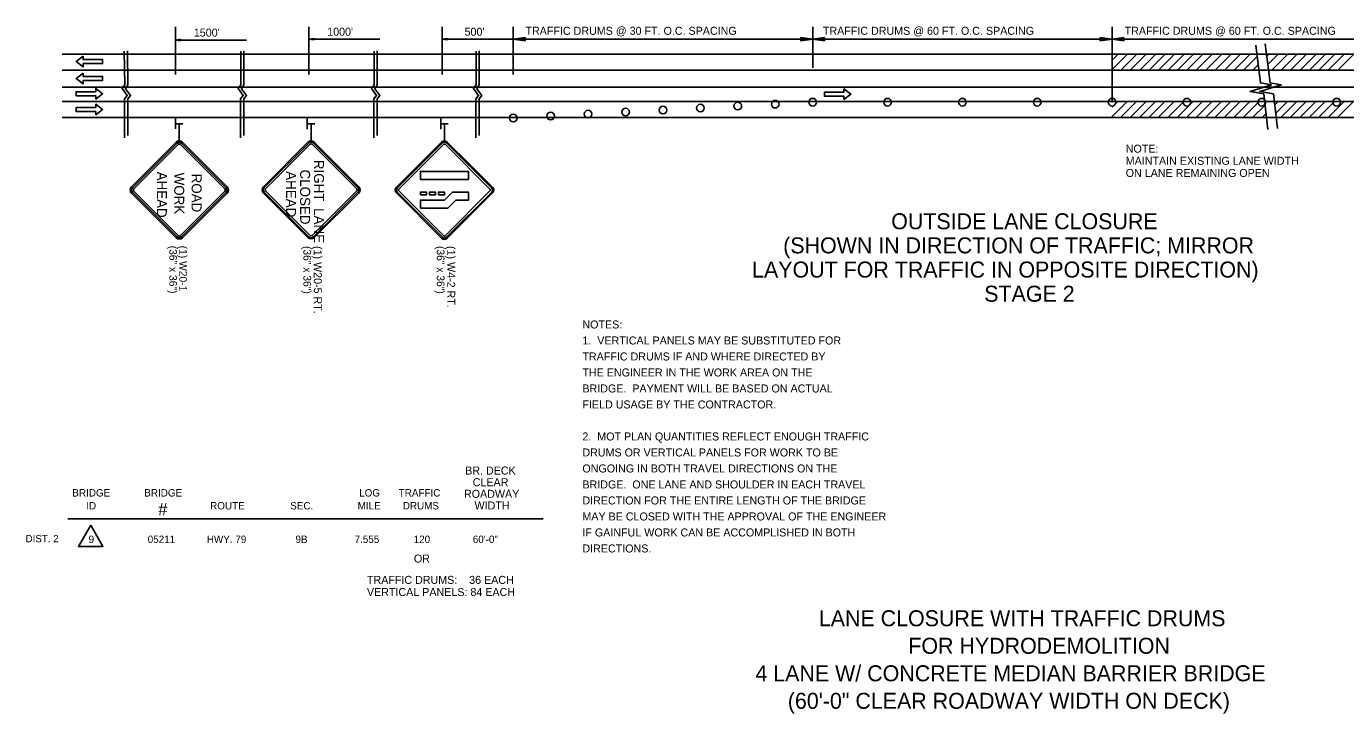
# Model space of a CAD drawing. Extents: x 1930579 to 1937984, y 596452 to 597630.
# Drawn here: x 1936426 to 1937415, y 596614 to 597129 of the extents above; entities that cross this region are included whole.
import ezdxf

# ---------------------------------------------------------------- set-up
doc = ezdxf.new("R2010")
doc.units = 0
for name, color, linetype in [('Default', 7, 'Continuous'), ('P_TC_Signs_Permanent', 7, 'Continuous'), ('P_TC_Signs_Temporary', 7, 'Continuous'), ('R_Border', 7, 'Continuous'), ('R_Striping', 7, 'Continuous')]:
    doc.layers.add(name, color=color, linetype=linetype)

msp = doc.modelspace()

# ---------------------------------------------------------------- linework, layer by layer
at = {"layer": 'Default'}
for p, q in [((1936537.79, 597129.19), (1936537.79, 597093.28)), ((1936637.79, 597129.19), (1936637.79, 597093.28)), ((1936737.79, 597129.19), (1936737.79, 597093.28)), ((1936791.02, 597129.19), (1936791.02, 597093.28)), ((1937015.53, 597129.19), (1937015.53, 597098.47)), ((1937240.04, 597129.19), (1937240.04, 597073.09)), ((1936541.62, 597119.78), (1936537.79, 597119.21)), ((1936537.79, 597119.21), (1936591.02, 597119.21)), ((1936541.62, 597118.63), (1936537.79, 597119.21)), ((1936541.62, 597119.68), (1936538.43, 597119.21)), ((1936541.62, 597118.73), (1936538.43, 597119.21)), ((1936541.62, 597119.59), (1936539.09, 597119.21)), ((1936541.62, 597118.83), (1936539.09, 597119.21)), ((1936541.62, 597119.49), (1936539.73, 597119.21)), ((1936541.62, 597118.92), (1936539.73, 597119.21)), ((1936541.62, 597119.39), (1936540.37, 597119.21)), ((1936541.62, 597119.02), (1936540.37, 597119.21)), ((1936541.62, 597119.3), (1936541.01, 597119.21)), ((1936541.62, 597119.12), (1936541.01, 597119.21)), ((1936541.62, 597118.63), (1936541.62, 597119.78)), ((1936641.62, 597120.46), (1936637.79, 597119.89)), ((1936637.79, 597119.89), (1936691.02, 597119.89)), ((1936641.62, 597119.31), (1936637.79, 597119.89)), ((1936641.62, 597120.36), (1936638.43, 597119.89)), ((1936641.62, 597119.41), (1936638.43, 597119.89)), ((1936641.62, 597120.27), (1936639.09, 597119.89)), ((1936641.62, 597119.51), (1936639.09, 597119.89)), ((1936641.62, 597120.17), (1936639.73, 597119.89)), ((1936641.62, 597119.6), (1936639.73, 597119.89)), ((1936641.62, 597120.07), (1936640.37, 597119.89)), ((1936641.62, 597119.7), (1936640.37, 597119.89)), ((1936641.62, 597119.98), (1936641.01, 597119.89)), ((1936641.62, 597119.8), (1936641.01, 597119.89)), ((1936641.62, 597119.31), (1936641.62, 597120.46)), ((1936741.62, 597120.46), (1936737.79, 597119.89)), ((1936737.79, 597119.89), (1936791.02, 597119.89)), ((1936741.62, 597119.31), (1936737.79, 597119.89)), ((1936741.62, 597120.36), (1936738.43, 597119.89)), ((1936741.62, 597119.41), (1936738.43, 597119.89)), ((1936741.62, 597120.27), (1936739.09, 597119.89)), ((1936741.62, 597119.51), (1936739.09, 597119.89)), ((1936741.62, 597120.17), (1936739.73, 597119.89)), ((1936741.62, 597119.6), (1936739.73, 597119.89)), ((1936741.62, 597120.07), (1936740.37, 597119.89)), ((1936741.62, 597119.7), (1936740.37, 597119.89)), ((1936741.62, 597119.98), (1936741.01, 597119.89)), ((1936741.62, 597119.8), (1936741.01, 597119.89)), ((1936741.62, 597119.31), (1936741.62, 597120.46)), ((1936791.02, 597119.89), (1936799.89, 597121.22)), ((1937015.53, 597119.89), (1936791.02, 597119.89)), ((1936799.89, 597118.56), (1936791.02, 597119.89)), ((1936799.89, 597121.22), (1936799.89, 597118.56)), ((1937015.53, 597119.89), (1937006.66, 597121.22)), ((1937006.66, 597121.22), (1937006.66, 597118.56)), ((1937006.66, 597118.56), (1937015.53, 597119.89)), ((1937015.53, 597119.89), (1937024.4, 597121.22)), ((1937240.04, 597119.89), (1937015.53, 597119.89)), ((1937024.4, 597118.56), (1937015.53, 597119.89)), ((1937024.4, 597121.22), (1937024.4, 597118.56)), ((1937231.17, 597118.56), (1937231.17, 597121.22)), ((1937231.17, 597121.22), (1937240.04, 597119.89)), ((1937240.04, 597119.89), (1937231.17, 597118.56)), ((1937248.9, 597121.22), (1937240.04, 597119.89)), ((1937464.54, 597119.89), (1937240.04, 597119.89)), ((1937240.04, 597119.89), (1937248.9, 597118.56)), ((1937248.9, 597118.56), (1937248.9, 597121.22)), ((1937804.86, 597108.65), (1936452.69, 597108.65)), ((1937240.04, 597097.16), (1937251.53, 597108.65)), ((1937240.04, 597104.23), (1937244.46, 597108.65)), ((1937246.6, 597096.65), (1937258.6, 597108.65)), ((1937253.67, 597096.65), (1937265.67, 597108.65)), ((1937260.74, 597096.65), (1937272.74, 597108.65)), ((1937267.81, 597096.65), (1937279.81, 597108.65)), ((1937274.88, 597096.65), (1937286.88, 597108.65)), ((1937281.95, 597096.65), (1937293.95, 597108.65)), ((1937289.02, 597096.65), (1937301.02, 597108.65)), ((1937296.09, 597096.65), (1937308.09, 597108.65)), ((1937303.17, 597096.65), (1937315.17, 597108.65)), ((1937310.24, 597096.65), (1937322.24, 597108.65)), ((1937317.31, 597096.65), (1937329.31, 597108.65)), ((1937324.38, 597096.65), (1937336.38, 597108.65)), ((1937331.45, 597096.65), (1937343.45, 597108.65)), ((1937338.52, 597096.65), (1937348.79, 597106.92)), ((1937356.05, 597107.11), (1937357.59, 597108.65)), ((1937356.84, 597100.83), (1937364.66, 597108.65)), ((1937359.73, 597096.65), (1937371.73, 597108.65)), ((1937366.81, 597096.65), (1937378.81, 597108.65)), ((1937373.88, 597096.65), (1937385.88, 597108.65)), ((1937380.95, 597096.65), (1937392.95, 597108.65)), ((1937388.02, 597096.65), (1937400.02, 597108.65)), ((1937395.09, 597096.65), (1937407.09, 597108.65)), ((1937402.16, 597096.65), (1937414.16, 597108.65)), ((1937409.23, 597096.65), (1937421.23, 597108.65)), ((1937345.59, 597096.65), (1937349.58, 597100.64)), ((1937804.86, 597096.65), (1936452.69, 597096.65)), ((1937804.86, 597083.85), (1936452.69, 597083.85)), ((1937350.85, 597080.7), (1937350.89, 597080.74)), ((1937804.86, 597073.09), (1936452.69, 597073.09)), ((1937239.31, 597061.09), (1937251.31, 597073.09)), ((1937240.04, 597068.88), (1937244.24, 597073.09)), ((1937246.39, 597061.09), (1937258.39, 597073.09)), ((1937253.46, 597061.09), (1937265.46, 597073.09)), ((1937260.53, 597061.09), (1937272.53, 597073.09)), ((1937267.6, 597061.09), (1937279.6, 597073.09)), ((1937274.67, 597061.09), (1937286.67, 597073.09)), ((1937281.74, 597061.09), (1937293.74, 597073.09)), ((1937288.81, 597061.09), (1937300.81, 597073.09)), ((1937295.88, 597061.09), (1937307.88, 597073.09)), ((1937302.95, 597061.09), (1937314.95, 597073.09)), ((1937310.03, 597061.09), (1937322.03, 597073.09)), ((1937317.1, 597061.09), (1937329.1, 597073.09)), ((1937324.17, 597061.09), (1937336.17, 597073.09)), ((1937331.24, 597061.09), (1937343.24, 597073.09)), ((1937338.31, 597061.09), (1937350.31, 597073.09)), ((1937345.38, 597061.09), (1937354.71, 597070.42)), ((1937361.97, 597070.61), (1937364.45, 597073.09)), ((1937362.73, 597064.29), (1937371.52, 597073.09)), ((1937366.59, 597061.09), (1937378.59, 597073.09)), ((1937373.67, 597061.09), (1937385.67, 597073.09)), ((1937380.74, 597061.09), (1937392.74, 597073.09)), ((1937387.81, 597061.09), (1937399.81, 597073.09)), ((1937394.88, 597061.09), (1937406.88, 597073.09)), ((1937401.95, 597061.09), (1937413.95, 597073.09)), ((1937409.02, 597061.09), (1937421.02, 597073.09)), ((1937804.86, 597061.09), (1936452.69, 597061.09)), ((1936537.79, 597052.49), (1936537.79, 597060.47)), ((1936636.62, 597052.43), (1936636.62, 597060.41)), ((1936736.62, 597052.43), (1936736.62, 597060.41)), ((1937352.45, 597061.09), (1937355.47, 597064.1)), ((1936537.91, 597056.46), (1936543.36, 597056.46)), ((1936636.74, 597056.4), (1936642.18, 597056.4)), ((1936736.74, 597056.4), (1936742.18, 597056.4))]:
    msp.add_line(p, q, dxfattribs=at)
for points in [[(1936499.33, 597110.93), (1936499.72, 597085.69), (1936497.77, 597082.8), (1936501.57, 597077.6), (1936499.57, 597075.2), (1936499.56, 597045.85)], [(1936501.73, 597111.16), (1936502.12, 597085.59), (1936500.17, 597082.7), (1936503.96, 597077.5), (1936501.96, 597075.1), (1936501.96, 597047.54)], [(1936586.69, 597110.93), (1936586.69, 597085.69), (1936584.74, 597082.8), (1936588.54, 597077.6), (1936586.54, 597075.2), (1936586.54, 597045.85)], [(1936589.09, 597111.16), (1936589.09, 597085.59), (1936587.14, 597082.7), (1936590.94, 597077.5), (1936588.94, 597075.1), (1936588.94, 597047.54)], [(1936686.69, 597110.93), (1936686.69, 597085.69), (1936684.74, 597082.8), (1936688.54, 597077.6), (1936686.54, 597075.2), (1936686.54, 597045.85)], [(1936689.09, 597111.16), (1936689.09, 597085.59), (1936687.14, 597082.7), (1936690.94, 597077.5), (1936688.94, 597075.1), (1936688.94, 597047.54)], [(1936763.16, 597110.93), (1936763.16, 597085.69), (1936761.21, 597082.8), (1936765.01, 597077.6), (1936763.01, 597075.2), (1936763, 597045.85)], [(1936765.56, 597111.16), (1936765.56, 597085.59), (1936763.61, 597082.7), (1936767.4, 597077.5), (1936765.41, 597075.1), (1936765.4, 597047.54)], [(1937347.74, 597115.35), (1937351.28, 597087.03), (1937359.53, 597085.57), (1937343.51, 597080.71), (1937353.71, 597078.77), (1937356.93, 597052)], [(1937354.91, 597116.24), (1937358.56, 597087.03), (1937366.82, 597085.57), (1937350.79, 597080.71), (1937360.99, 597078.77), (1937364.11, 597052.86)]]:
    msp.add_lwpolyline(points, dxfattribs=at)
for centre in [(1936875.21, 597065.17), (1936903.28, 597066.66), (1936931.34, 597068.14), (1936959.4, 597069.63), (1936987.47, 597071.11), (1937015.53, 597072.6), (1937071.66, 597072.6), (1937127.78, 597072.6), (1937183.91, 597072.6), (1937240.04, 597072.6), (1937296.16, 597072.6), (1937352.29, 597072.6), (1937408.42, 597072.6), (1936791.02, 597060.71), (1936819.09, 597062.2), (1936847.15, 597063.68)]:
    msp.add_circle(centre, 2.87, dxfattribs=at)
at = {"layer": 'P_TC_Signs_Permanent'}
for p, q in [((1936703.4, 597008.78), (1936737.34, 597042.72)), ((1936757.46, 597014.7), (1936757.46, 597020.7)), ((1936737.34, 596970.6), (1936703.4, 597004.54)), ((1936775.52, 597004.54), (1936741.58, 596970.6))]:
    msp.add_line(p, q, dxfattribs=at)
for points in [[(1936737.97, 597042.08), (1936704.03, 597008.14)], [(1936705.09, 597007.08), (1936739.04, 597041.02)], [(1936739.88, 597041.02), (1936773.82, 597007.08)], [(1936774.89, 597008.14), (1936740.94, 597042.08)], [(1936741.58, 597042.72), (1936758.55, 597025.75), (1936775.52, 597008.78)], [(1936704.03, 597005.17), (1936737.97, 596971.23)], [(1936739.04, 596972.29), (1936705.09, 597006.23)], [(1936773.82, 597006.23), (1936739.88, 596972.29)], [(1936740.94, 596971.23), (1936774.89, 597005.17)]]:
    msp.add_lwpolyline(points, dxfattribs=at)
for points in [[(1936721.46, 597014.7), (1936721.46, 597020.7), (1936757.46, 597020.7), (1936757.46, 597014.7)], [(1936721.46, 597003.06), (1936721.46, 597005.16), (1936725.96, 597005.16), (1936725.96, 597003.06)], [(1936721.46, 596993.16), (1936721.46, 596999.16), (1936739.46, 596999.16), (1936745.46, 597005.16), (1936757.46, 597005.16), (1936757.46, 596999.16), (1936747.94, 596999.16), (1936741.94, 596993.16)], [(1936728.21, 597003.06), (1936728.21, 597005.16), (1936732.71, 597005.16), (1936732.71, 597003.06)], [(1936734.96, 597003.06), (1936734.96, 597005.16), (1936739.46, 597005.16), (1936739.46, 597003.06)]]:
    msp.add_lwpolyline(points, close=True, dxfattribs=at)
for centre, radius, start, end in [((1936739.46, 597040.6), 3, 45, 135), ((1936739.46, 597040.6), 2.1, 45, 135), ((1936739.46, 597040.6), 0.6, 45, 135), ((1936705.52, 597006.66), 3, 135, 225), ((1936705.52, 597006.66), 2.1, 135, 225), ((1936773.4, 597006.66), 2.1, 315, 45), ((1936773.4, 597006.66), 3, 315, 45), ((1936705.52, 597006.66), 0.6, 135, 225), ((1936773.4, 597006.66), 0.6, 315, 45), ((1936739.46, 596972.72), 3, 225, 315), ((1936739.46, 596972.72), 2.1, 225, 315), ((1936739.46, 596972.72), 0.6, 225, 315)]:
    msp.add_arc(centre, radius, start, end, dxfattribs=at)
at = {"layer": 'P_TC_Signs_Temporary'}
for p, q in [((1936504.84, 597009.13), (1936538.25, 597042.54)), ((1936505.5, 597008.46), (1936538.91, 597041.88)), ((1936506.43, 597007.54), (1936539.84, 597040.95)), ((1936541.43, 597040.95), (1936574.84, 597007.54)), ((1936542.36, 597041.88), (1936575.77, 597008.46)), ((1936543.02, 597042.54), (1936576.43, 597009.13)), ((1936603.66, 597009.2), (1936637.07, 597042.61)), ((1936604.33, 597008.54), (1936637.74, 597041.95)), ((1936605.25, 597007.61), (1936638.66, 597041.02)), ((1936640.26, 597041.02), (1936673.67, 597007.61)), ((1936641.18, 597041.95), (1936674.59, 597008.54)), ((1936641.85, 597042.61), (1936675.26, 597009.2)), ((1936538.25, 596970.94), (1936504.84, 597004.35)), ((1936538.91, 596971.61), (1936505.5, 597005.02)), ((1936539.84, 596972.53), (1936506.43, 597005.95)), ((1936574.84, 597005.95), (1936541.43, 596972.53)), ((1936575.77, 597005.02), (1936542.36, 596971.61)), ((1936576.43, 597004.35), (1936543.02, 596970.94)), ((1936637.07, 596971.02), (1936603.66, 597004.43)), ((1936637.74, 596971.68), (1936604.33, 597005.09)), ((1936638.66, 596972.61), (1936605.25, 597006.02)), ((1936673.67, 597006.02), (1936640.26, 596972.61)), ((1936674.59, 597005.09), (1936641.18, 596971.68)), ((1936675.26, 597004.43), (1936641.85, 596971.02))]:
    msp.add_line(p, q, dxfattribs=at)
for centre, radius, start, end in [((1936540.63, 597040.15), 3.38, 45, 135), ((1936540.63, 597040.15), 2.44, 45, 135), ((1936540.63, 597040.15), 1.12, 45, 135), ((1936639.46, 597040.22), 3.38, 45, 135), ((1936639.46, 597040.22), 2.44, 45, 135), ((1936639.46, 597040.22), 1.12, 45, 135), ((1936507.22, 597006.74), 3.38, 135, 225), ((1936507.22, 597006.74), 2.44, 135, 225), ((1936574.04, 597006.74), 2.44, 315, 45), ((1936574.04, 597006.74), 3.38, 315, 45), ((1936606.05, 597006.81), 3.38, 135, 225), ((1936606.05, 597006.81), 2.44, 135, 225), ((1936672.87, 597006.81), 2.44, 315, 45), ((1936672.87, 597006.81), 3.38, 315, 45), ((1936507.22, 597006.74), 1.13, 135, 225), ((1936574.04, 597006.74), 1.13, 315, 45), ((1936606.05, 597006.81), 1.13, 135, 225), ((1936672.87, 597006.81), 1.13, 315, 45), ((1936540.63, 596973.33), 3.38, 225, 315), ((1936540.63, 596973.33), 2.44, 225, 315), ((1936540.63, 596973.33), 1.12, 225, 315), ((1936639.46, 596973.4), 3.38, 225, 315), ((1936639.46, 596973.4), 2.44, 225, 315), ((1936639.46, 596973.4), 1.12, 225, 315)]:
    msp.add_arc(centre, radius, start, end, dxfattribs=at)
at = {"layer": 'R_Border'}
for p, q in [((1936540.63, 597056.46), (1936540.63, 597043.53)), ((1936639.46, 597056.4), (1936639.46, 597043.6)), ((1936739.46, 597056.4), (1936739.46, 597043.6)), ((1936457.05, 596760.2), (1936813.4, 596760.2))]:
    msp.add_line(p, q, dxfattribs=at)
msp.add_lwpolyline([(1936474.19, 596755.38), (1936464.98, 596739.42), (1936464.98, 596739.42), (1936483.39, 596739.42)], close=True, dxfattribs=at)
at = {"layer": 'R_Striping'}
for points in [[(1936468.42, 597107.02), (1936463.23, 597103.02), (1936468.42, 597099.02), (1936468.42, 597101.52), (1936483.13, 597101.52), (1936483.13, 597104.52), (1936468.42, 597104.52)], [(1936468.42, 597094.38), (1936463.23, 597090.38), (1936468.42, 597086.38), (1936468.42, 597088.88), (1936483.13, 597088.88), (1936483.13, 597091.88), (1936468.42, 597091.88)], [(1936477.94, 597074.88), (1936483.13, 597078.88), (1936477.94, 597082.88), (1936477.94, 597080.38), (1936463.23, 597080.38), (1936463.23, 597077.38), (1936477.94, 597077.38)], [(1937038.98, 597074.5), (1937044.17, 597078.5), (1937038.98, 597082.5), (1937038.98, 597080), (1937024.27, 597080), (1937024.27, 597077), (1937038.98, 597077)], [(1936477.94, 597063.1), (1936483.13, 597067.1), (1936477.94, 597071.1), (1936477.94, 597068.6), (1936463.23, 597068.6), (1936463.23, 597065.6), (1936477.94, 597065.6)]]:
    msp.add_lwpolyline(points, close=True, dxfattribs=at)

# ---------------------------------------------------------------- texts
at = {"layer": 'Default'}
for s, height, p in [("1500'", 6, (1936551.51, 597121.78)), ("1000'", 6, (1936651.51, 597122.45)), ("500'", 6, (1936754.51, 597122.45)), ('TRAFFIC DRUMS @ 30 FT. O.C. SPACING', 6, (1936800.17, 597123.14)), ('TRAFFIC DRUMS @ 60 FT. O.C. SPACING', 6, (1937023.16, 597123.14)), ('TRAFFIC DRUMS @ 60 FT. O.C. SPACING', 6, (1937249.43, 597123.14)), ('OUTSIDE LANE CLOSURE', 12, (1937074.43, 596977.28)), ('(SHOWN IN DIRECTION OF TRAFFIC; MIRROR', 12, (1936993.41, 596959.17)), (' LAYOUT FOR TRAFFIC IN OPPOSITE DIRECTION)', 12, (1936965.63, 596941.05)), ('STAGE 2', 12, (1937144.16, 596922.93)), ('LANE CLOSURE WITH TRAFFIC DRUMS', 12, (1937020.12, 596679.5)), ('FOR HYDRODEMOLITION', 12, (1937087.25, 596658.86)), ('4 LANE W/ CONCRETE MEDIAN BARRIER BRIDGE', 12, (1936972.59, 596638.22)), ('(60\'-0" CLEAR ROADWAY WIDTH ON DECK)', 12, (1936996.87, 596617.58))]:
    msp.add_text(s, height=height, rotation=360, dxfattribs=at).set_placement(p)
at = {"layer": 'P_TC_Signs_Temporary'}
for s, p in [('RIGHT\u2002LANE', (1936641.59, 597029.33)), (' AHEAD ', (1936523.8, 597023.28)), ('WORK', (1936536.82, 597019.73)), (' ROAD ', (1936549.85, 597021.76)), (' AHEAD ', (1936620.71, 597023.59)), ('CLOSED', (1936631.21, 597022.07))]:
    msp.add_text(s, height=7.5, rotation=270, dxfattribs=at).set_placement(p)
at = {"layer": 'R_Border'}
for s, height, rotation, p in [('NOTE:', 6, 360, (1937250.26, 597034.72)), ('MAINTAIN EXISTING LANE WIDTH', 6, 360, (1937250.26, 597025.61)), ('ON LANE REMAINING OPEN', 6, 360, (1937250.26, 597016.5)), ('(36" x 36")', 5.76, 270, (1936533.14, 596964.96)), ('(1) W20-1', 5.76, 270, (1936540.63, 596964.96)), ('(36" x 36")', 5.76, 270, (1936633.7, 596964.72)), ('(1) W20-5 RT.', 6, 270, (1936641.47, 596964.72)), ('(36" x 36")', 5.76, 270, (1936733.7, 596964.72)), ('(1) W4-2 RT.', 6, 270, (1936741.47, 596964.72)), ('NOTES:', 6, 360, (1936842.87, 596902.86)), ('1.  VERTICAL PANELS MAY BE SUBSTITUTED FOR', 6, 360, (1936842.87, 596890.86)), ('TRAFFIC DRUMS IF AND WHERE DIRECTED BY', 6, 360, (1936842.87, 596878.86)), ('THE ENGINEER IN THE WORK AREA ON THE ', 6, 360, (1936842.87, 596866.86)), ('BRIDGE.  PAYMENT WILL BE BASED ON ACTUAL ', 6, 360, (1936842.87, 596854.86)), ('FIELD USAGE BY THE CONTRACTOR.', 6, 360, (1936842.87, 596842.86)), ('2.  MOT PLAN QUANTITIES REFLECT ENOUGH TRAFFIC', 6, 360, (1936842.87, 596818.86)), ('DRUMS OR VERTICAL PANELS FOR WORK TO BE', 6, 360, (1936842.87, 596806.86)), ('ONGOING IN BOTH TRAVEL DIRECTIONS ON THE ', 6, 360, (1936842.87, 596794.86)), ('BR. DECK', 6, 360, (1936754.98, 596793.3)), ('CLEAR ', 6, 360, (1936760.63, 596784.56)), ('BRIDGE', 5.54, 360, (1936460.43, 596776.82)), ('BRIDGE', 5.54, 360, (1936514.36, 596776.82)), ('LOG', 5.54, 360, (1936675.5, 596776.82)), ('TRAFFIC', 5.54, 360, (1936705.12, 596776.82)), ('ROADWAY ', 6, 360, (1936754.09, 596775.83)), ('BRIDGE.  ONE LANE AND SHOULDER IN EACH TRAVEL', 6, 360, (1936842.87, 596782.86)), ('ID', 5.54, 360, (1936470.87, 596767.13)), ('#', 9.36, 360, (1936524.8, 596762.65)), ('ROUTE', 5.54, 360, (1936563.74, 596767.13)), ('SEC.', 5.54, 360, (1936623.77, 596767.13)), ('MILE', 5.54, 360, (1936674.34, 596767.13)), ('DRUMS', 5.54, 360, (1936708.19, 596767.13)), ('WIDTH', 6, 360, (1936761.98, 596767.09)), ('DIRECTION FOR THE ENTIRE LENGTH OF THE BRIDGE', 6, 360, (1936842.87, 596770.86)), ('MAY BE CLOSED WITH THE APPROVAL OF THE ENGINEER', 6, 360, (1936842.87, 596758.86)), ('IF GAINFUL WORK CAN BE ACCOMPLISHED IN BOTH', 6, 360, (1936842.87, 596746.86)), ('DIST. 2', 5.47, 360, (1936425.37, 596742.49)), ('DIRECTIONS.', 6, 360, (1936842.87, 596734.86)), ('OR', 6, 360, (1936716.52, 596727.29)), ('TRAFFIC DRUMS:    36 EACH', 6, 360, (1936681.32, 596711.29)), ('VERTICAL PANELS: 84 EACH', 6, 360, (1936681.32, 596702.18))]:
    msp.add_text(s, height=height, rotation=rotation, dxfattribs=at).set_placement(p)
for s, p in [('9', (1936472.6, 596741.97)), ('05211', (1936516.92, 596741.97)), ('HWY. 79', (1936561.23, 596741.97)), ('9B', (1936627.71, 596741.97)), ('7.555', (1936672.03, 596741.97)), ('120', (1936716.35, 596741.97)), ('60\'-0"', (1936760.67, 596741.97))]:
    msp.add_text(s, height=5.54, dxfattribs=at).set_placement(p)

doc.saveas('drawing.dxf')
